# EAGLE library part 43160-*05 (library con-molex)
SDA-43160 Connector Source: http://www.molex.com/pdm_docs/sd/431601306_sd.pdf
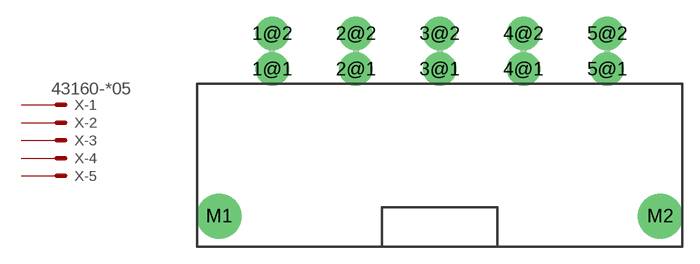
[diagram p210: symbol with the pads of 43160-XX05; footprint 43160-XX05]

Designator prefix X; gates -1=MV2 -2=M2 -3=M2 -4=M2 -5=M2

## 43160-1105 (MF: WALDOM/MOLEX; MPN: 43160-1105; OC_FARNELL: unknown; OC_NEWARK: 54H0258), 43160-1205 (OC_FARNELL: unknown; OC_NEWARK: unknown), 43160-1305 (MPN: 43160-1305; OC_FARNELL: unknown; OC_NEWARK: 92M1483), 43160-1405 (OC_FARNELL: unknown; OC_NEWARK: unknown), 43160-3105 (MF: WALDOM/MOLEX; MPN: 43160-3105; OC_FARNELL: unknown; OC_NEWARK: 54H0267), 43160-3205 (OC_FARNELL: unknown; OC_NEWARK: unknown), 43160-5105 (MPN: 43160-5105; OC_FARNELL: unknown; OC_NEWARK: 92M1496), 43160-5205 (OC_FARNELL: unknown; OC_NEWARK: unknown), 43160-5305 (MPN: 43160-5305; OC_FARNELL: unknown; OC_NEWARK: 92M1501), 43160-5405 (OC_FARNELL: unknown; OC_NEWARK: unknown), 43160-7305 (MPN: 43160-7305; OC_FARNELL: unknown; OC_NEWARK: 92M1510), 43160-7405 (OC_FARNELL: unknown; OC_NEWARK: unknown)  [43160-XX05]
1@1  -1:S  pas
1@2  -1:S  pas
2@1  -2:S  pas
2@2  -2:S  pas
3@1  -3:S  pas
3@2  -3:S  pas
4@1  -4:S  pas
4@2  -4:S  pas
5@1  -5:S  pas
5@2  -5:S  pas

## Footprint 43160-XX05 (pad centres in mm)
SDA-43160 Connector Source: http://www.molex.com/pdm_docs/sd/431601306_sd.pdf
drill 1.8 pad 3 round: 1@1 -14.98,0; 1@2 -14.98,3.18; 2@1 -7.49,0; 2@2 -7.49,3.18; 3@1 0,0; 3@2 0,3.18; 4@1 7.49,0; 4@2 7.49,3.18; 5@1 14.98,0; 5@2 14.98,3.18
drill 3 pad 3.4 round: M1 -19.73,-13.13; M2 19.73,-13.13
